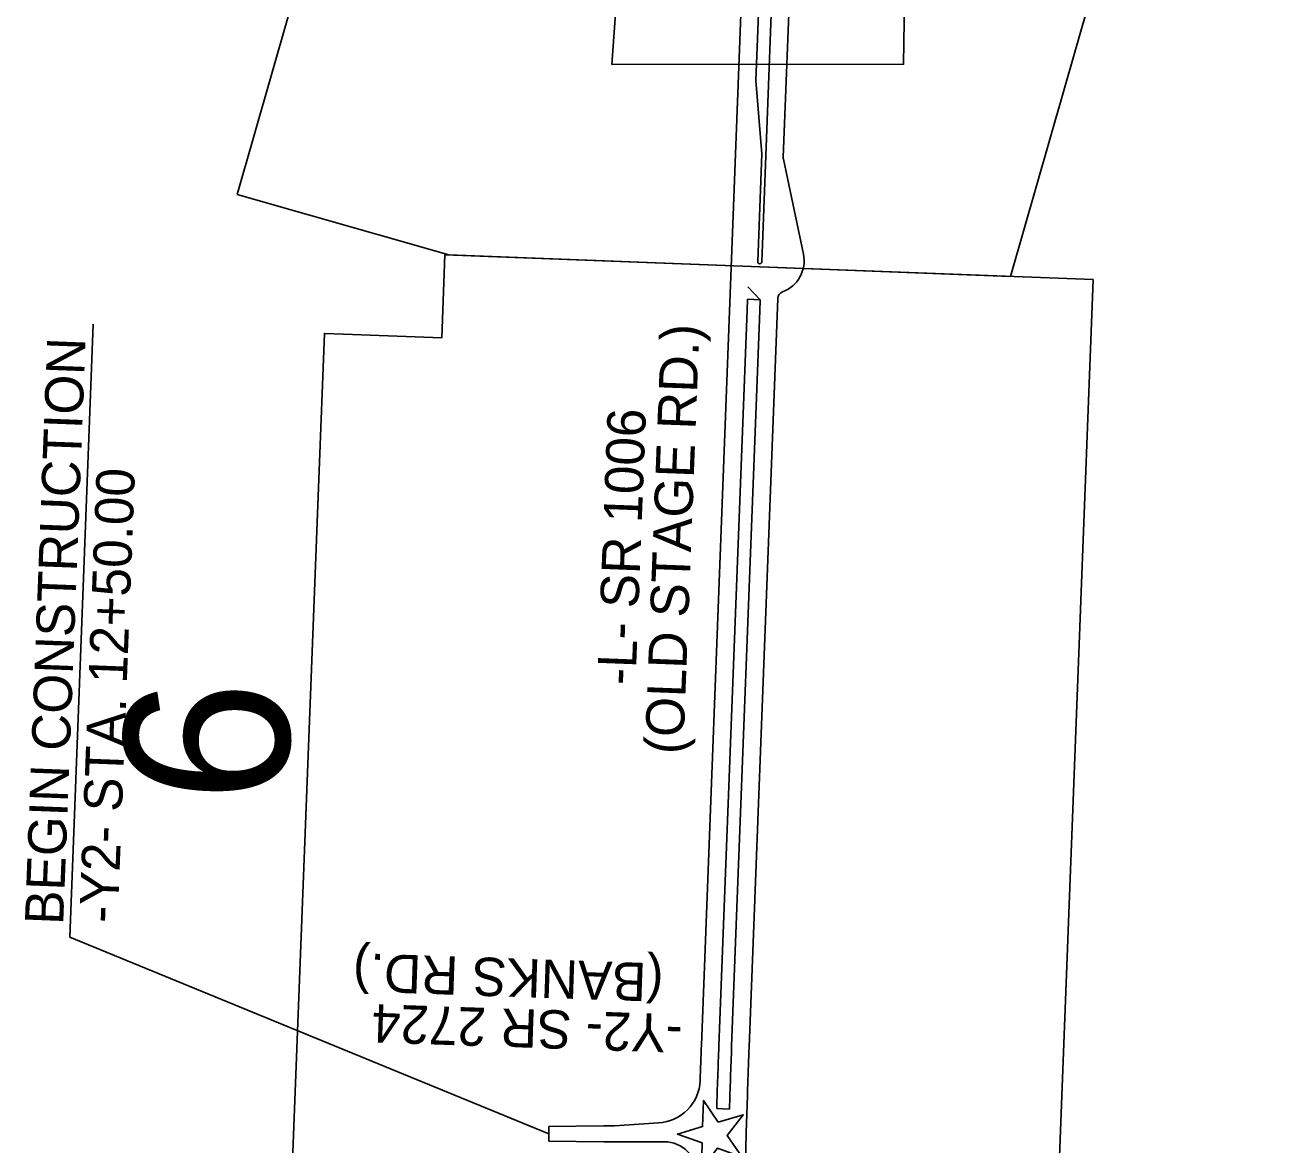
# Model space of a CAD drawing. Extents: x 2094564 to 2100382, y 679033 to 692366.
# Drawn here: x 2096767 to 2098480, y 686864 to 688399 of the extents above; entities that cross this region are included whole.
import ezdxf

# ---------------------------------------------------------------- set-up
doc = ezdxf.new("R2010")
doc.units = 0
for name, color, linetype in [('Pattern 17', 7, 'Continuous'), ('Prop Horizontal Alignment Direction Label', 7, 'Continuous'), ('Prop RDY Traffic Signal CELL', 7, 'Continuous'), ('Prop Shade Light', 7, 'Continuous'), ('Scratch_Level_0', 7, 'Continuous'), ('Scratch_Level_1', 7, 'Continuous'), ('Scratch_Level_3', 7, 'Continuous'), ('Scratch_Level_5', 7, 'Continuous')]:
    doc.layers.add(name, color=color, linetype=linetype)

msp = doc.modelspace()

# ---------------------------------------------------------------- linework, layer by layer
at = {"layer": 'Pattern 17'}
for points in [[(2098117.8, 688054.5), (2097347.7, 688084), (2097057.8, 688167), (2097360.5, 689224.4), (2097415.6, 689416.8), (2097440.8, 689409.5), (2097570.4, 689372.4), (2097625.5, 689564.8), (2098480.1, 689320.1)], [(2098179.2, 686705.4), (2097129.6, 686735.9), (2097169.5, 687776.6), (2097177.2, 687976.5), (2097203.4, 687975.5), (2097338.1, 687970.3), (2097342.5, 688084.2), (2098230.8, 688050.2)]]:
    msp.add_lwpolyline(points, close=True, dxfattribs=at)
at = {"layer": 'Prop RDY Traffic Signal CELL'}
msp.add_lwpolyline([(2097716.9, 686895.5), (2097696.6, 686925.2), (2097695.6, 686889.3), (2097661, 686879.1), (2097695, 686867), (2097693.9, 686831.1), (2097715.9, 686859.6), (2097749.7, 686847.5), (2097729.4, 686877.2), (2097751.4, 686905.7), (2097716.9, 686895.5)], dxfattribs=at)
at = {"layer": 'Prop Shade Light'}
for p, q in [((2097749.7, 688457.3), (2097693.9, 687001)), ((2097768.6, 688323.1), (2097773.7, 688456.4)), ((2097791.2, 688455.7), (2097776.6, 688074.6)), ((2097806.1, 688217.8), (2097815.2, 688454.8)), ((2097776.8, 688222.7), (2097768.6, 688323.1)), ((2097771.1, 688074.8), (2097776.8, 688222.7)), ((2097833.7, 688085), (2097806.3, 688215.4)), ((2097756.5, 688008.3), (2097757.1, 688023.3)), ((2097757.1, 688023.3), (2097774.6, 688022.6)), ((2097759.3, 686998.4), (2097798.7, 688024.5)), ((2097774.6, 688022.6), (2097774, 688007.6)), ((2097717.9, 687000), (2097756.5, 688008.3)), ((2097774, 688007.6), (2097735.4, 686999.4)), ((2097732.4, 686913.4), (2097714.9, 686914)), ((2097560, 686890.6), (2097485, 686889.6)), ((2097485, 686889.6), (2097485, 686869.3)), ((2097574.9, 686890.6), (2097560, 686890.6)), ((2097635, 686894.7), (2097574.9, 686890.6)), ((2097747.6, 686611.8), (2097755.9, 686896.8)), ((2097485, 686869.3), (2097560, 686868.6)), ((2097560, 686868.6), (2097643.2, 686868.6))]:
    msp.add_line(p, q, dxfattribs=at)
for centre, radius, start, end in [((2097816.1, 688217.4), 10, 177.8037, 191.8817), ((2097773.9, 688074.7), 2.75, 177.8037, 357.8037), ((2097789.7, 688075.7), 45, 290.1891, 11.8817), ((2097808.7, 688024.1), 10, 110.1891, 177.8037), ((2108718.5, 686578.1), 11032.7, 177.8037, 178.05499), ((2108718.5, 686578.1), 11008.7, 177.8037, 178.25147), ((2108718.5, 686578.1), 10991.2, 177.8037, 178.25219), ((2108718.5, 686578.1), 10967.2, 177.8037, 178.33483), ((2097632.2, 686954.6), 60, 272.6494, 358.055), ((2097643.2, 686823.6), 45, 358.3348, 90.016)]:
    msp.add_arc(centre, radius, start, end, dxfattribs=at)
at = {"layer": 'Scratch_Level_0'}
for p, q in [((2096828.3, 687148.8), (2096860.5, 687989)), ((2097485, 686879.6), (2096828.3, 687148.8))]:
    msp.add_line(p, q, dxfattribs=at)
at = {"layer": 'Scratch_Level_1'}
for p, q in [((2097774.6, 688022.6), (2097757.1, 688023.3)), ((2097714.9, 686914), (2097732.4, 686913.4))]:
    msp.add_line(p, q, dxfattribs=at)
at = {"layer": 'Scratch_Level_3'}
msp.add_line((2097757.8, 688040.3), (2097774.6, 688022.6), dxfattribs=at)
at = {"layer": 'Scratch_Level_5'}
msp.add_lwpolyline([(2097571, 688344.9), (2097971.1, 688345.3), (2097985.6, 689286.6), (2097972, 689290.3), (2097856.9, 689318.4), (2097629.8, 689153.8)], close=True, dxfattribs=at)

# ---------------------------------------------------------------- texts
at = {"layer": 'Prop Horizontal Alignment Direction Label'}
msp.add_text('6', height=225.9, rotation=87.8037, dxfattribs=at).set_placement((2097125.6, 687329.7))
at = {"layer": 'Scratch_Level_0'}
for s, height, rotation, p in [('(OLD STAGE RD.)', 52.563, 87.8037, (2097668.9, 687399.2)), ('BEGIN CONSTRUCTION', 52.591, 87.8037, (2096819.2, 687165.4)), ('-L- SR 1006', 52.563, 87.8037, (2097603.6, 687493.8)), ('-Y2- STA. 12+50.00', 52.591, 87.8037, (2096893.8, 687167.9)), ('(BANKS RD.)', 52.563, 178.0549, (2097642.6, 687112.8)), ('-Y2- SR 2724', 52.563, 178.0549, (2097669, 687042.9))]:
    msp.add_text(s, height=height, rotation=rotation, dxfattribs=at).set_placement(p)

doc.saveas('drawing.dxf')
